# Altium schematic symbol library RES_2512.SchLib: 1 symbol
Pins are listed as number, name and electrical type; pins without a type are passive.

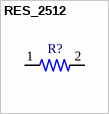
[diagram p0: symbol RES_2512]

## RES_2512
designator R?
2512 1% 1W; MP: 1-2176071-4
footprint RES_2512
pins: 1, 2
